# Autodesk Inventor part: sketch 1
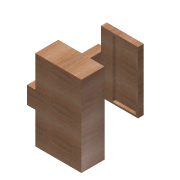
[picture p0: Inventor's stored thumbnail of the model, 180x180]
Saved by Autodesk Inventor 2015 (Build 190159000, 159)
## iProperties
Created: 2016-02
Part Number: sketch 1
Material: Wood (Birch)
Document SubType Name: Modeling
Designer: Hafliði
Density: 0.55 g/cm^3
Appearance: Birch - Natural Polished
Author: Hafliði
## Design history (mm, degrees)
sketch "Sketch1"
  geometry: L1 (-200, -350)-(200, -350); L2 (200, -350)-(200, 350); L3 (200, 350)-(-200, 350); L4 (-200, 350)-(-200, -350); L5 (-200, -350)-(200, 350); L6 (200, -350)-(-200, 350); 1 further point
  constraints: 12 end point, 2 midpoint, 2 parallel, 1 horizontal, 1 perpendicular
  dimensions: "d0" = 400 distance of L3.end L2.end; "d1" = 700 distance of L2.end L1.end
extrude "Extrusion1" new body sketch "Sketch1" distance "d2" = 10; taper "d3" = 0 deg
sketch "Sketch2"
  geometry: L1 (200, 350)-(-200, 350); L2 (-200, 350)-(-200, -350); L3 (-200, -350)-(200, -350); L4 (200, -350)-(200, 350); L5 (200, 350)-(-200, -350); L6 (-200, 350)-(200, -350); L7 (195, 345)-(-195, 345); L8 (-195, 345)-(-195, -345); L9 (-195, -345)-(195, -345); L10 (195, -345)-(195, 345); L11 (195, 345)-(-195, -345); L12 (-195, 345)-(195, -345); 1 further point
  constraints: 24 end point, 4 midpoint, 4 parallel, 2 horizontal, 2 perpendicular
  dimensions: "d4" = 400 distance of L3.end L2.end; "d5" = 700 distance of L2.end L1.end; "d6" = 390 distance of L9.end L8.end; "d7" = 690 distance of L8.end L7.end
extrude "Extrusion2" join sketch "Sketch2" distance "d8" = 190; taper "d9" = 0 deg
sketch "Sketch3"
  geometry: L1 (120, -270)-(195, -270); L2 (195, -270)-(195, -345); L3 (195, -345)-(120, -345); L4 (120, -345)-(120, -270); L5 (-195, -345)-(-120, -345); L6 (-120, -345)-(-120, -270); L7 (-120, -270)-(-195, -270); L8 (-195, -270)-(-195, -345); L9 (195, 345)-(115, 345); L10 (115, 345)-(115, 265); L11 (115, 265)-(195, 265); L12 (195, 265)-(195, 345); L13 (-195, 345)-(-115, 345); L14 (-115, 345)-(-115, 265); L15 (-115, 265)-(-195, 265); L16 (-195, 265)-(-195, 345); 3 further points
  constraints: 32 end point, 8 parallel, 4 horizontal, 4 perpendicular
  dimensions: "d12" = 75 distance of L2.end L3.end; "d13" = 75 distance of L1.end L2.end; "d16" = 80 distance of L11.end L10.end; "d17" = 80 distance of L10.end L9.end; "d18" = 80 distance of L14.end L15.end; "d19" = 80 distance of L13.end L14.end
extrude "Extrusion3" join sketch "Sketch3" distance "d20" = 190; taper "d21" = 0 deg
sketch "Sketch4"
  geometry: L1 (200, -350)-(200, 350) reference; L2 (200, 0)-(200, -75); L3 (200, -75)-(272, -75); L4 (272, -75)-(272, 75); L5 (272, 75)-(200, 75); L6 (200, 75)-(200, -75); 1 further point
  constraints: 10 end point, 2 parallel, 1 horizontal, 1 midpoint, 1 perpendicular, 1 point on line
extrude "Extrusion4" join sketch "Sketch4" distance "d23" = 620; taper "d24" = 0 deg
sketch "Sketch5"
  geometry: L1 (-200, 350)-(-200, 75) reference; L2 (-200, 265)-(120, 265); L3 (120, 265)-(120, -270); L4 (120, -270)-(-200, -270); L5 (-200, -270)-(-200, 265); 1 further point
  constraints: 8 end point, 2 parallel, 1 horizontal, 1 perpendicular, 1 point on line
extrude "Extrusion5" join sketch "Sketch5" distance "d25" = 50; taper "d26" = 0 deg
sketch "Sketch7"
  geometry: L1 (-100, 250)-(100, 250); L2 (100, 250)-(100, -250); L3 (100, -250)-(-100, -250); L4 (-100, -250)-(-100, 250); L5 (-100, 250)-(100, -250); L6 (100, 250)-(-100, -250); 1 further point
  constraints: 12 end point, 2 midpoint, 2 parallel, 1 horizontal, 1 perpendicular
  dimensions: "d31" = 200 distance of L2.end L3.end; "d32" = 500 distance of L1.end L2.end
extrude "Extrusion7" cut sketch "Sketch7" distance "d33" = 25; taper "d34" = 0 deg
body "Solid1"
